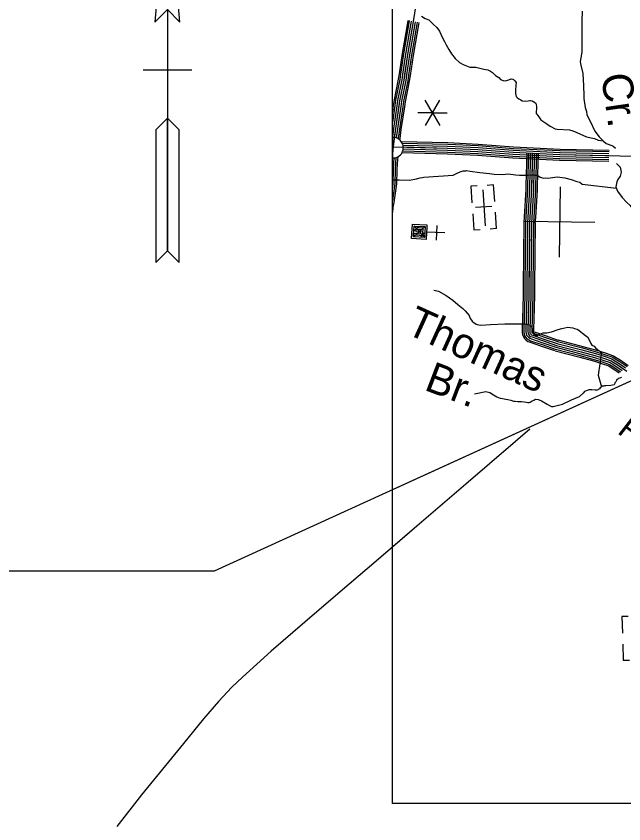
# Model space of a CAD drawing. Extents: x 1577619 to 1828281, y 483481 to 598136.
# Drawn here: x 1663305 to 1672781, y 507802 to 520403 of the extents above; entities that cross this region are included whole.
import ezdxf

# ---------------------------------------------------------------- set-up
doc = ezdxf.new("R2010")
doc.units = 0
for name, color, linetype in [('DESIGN - CENTERLINE - Proposed', 7, 'Continuous'), ('DESIGN - CENTERLINE - Proposed Text', 7, 'Continuous'), ('DESIGN - DRAINAGE - Bridges and Cross Drains Size Text', 7, 'Continuous'), ('DESIGN - ROW - Right-of-Way and Easement Labels', 7, 'Continuous'), ('DESIGN - SHEET - Linework', 7, 'Continuous'), ('DESIGN - TRAFFIC CONTROL PERMANENT - Signalization', 7, 'Continuous'), ('DESIGN - TRANSPORTATION - Text', 7, 'Continuous'), ('DESIGN - UTILITIES - Cable (Underground) with Text', 7, 'Continuous'), ('SURVEY - CENTERLINE - Preliminary Text', 7, 'Continuous'), ('SURVEY - CONTROL with Text', 7, 'Continuous'), ('SURVEY - DRAINAGE - Bridge Hydraulic Data - Points - Locators', 7, 'Continuous'), ('SURVEY - TRANSPORTATION - Roads', 7, 'Continuous'), ('SURVEY - VEGETATION - Features with Text', 7, 'Continuous')]:
    doc.layers.add(name, color=color, linetype=linetype)

msp = doc.modelspace()

# ---------------------------------------------------------------- linework, layer by layer
at = {"layer": 'DESIGN - CENTERLINE - Proposed'}
for p, q in [((1665664, 519561), (1665286, 519561)), ((1666042, 519561), (1665664, 519561))]:
    msp.add_line(p, q, dxfattribs=at)
msp.add_lwpolyline([(1665664, 522561), (1665468, 520309), (1665664, 520505), (1665860, 520309), (1665664, 522561), (1665664, 516743), (1665846, 516561), (1665846, 518631), (1665664, 518813), (1665482, 518631), (1665482, 516561), (1665664, 516743)], dxfattribs=at)
for points in [[(1665664, 520505), (1665860, 520309), (1665664, 522561)], [(1665482, 516561), (1665664, 516743), (1665664, 518813), (1665482, 518631)]]:
    msp.add_lwpolyline(points, close=True, dxfattribs=at)
at = {"layer": 'DESIGN - CENTERLINE - Proposed Text'}
for points in [[(1680381, 518131), (1666391, 511746), (1653607, 511746)], [(1680381, 518131), (1669172, 513015)]]:
    msp.add_lwpolyline(points, dxfattribs=at)
at = {"layer": 'DESIGN - SHEET - Linework'}
msp.add_lwpolyline([(1669172, 526511), (1695618, 526511), (1695618, 508120), (1669172, 508120)], close=True, dxfattribs=at)
at = {"layer": 'DESIGN - TRAFFIC CONTROL PERMANENT - Signalization'}
for q in [(1669682, 519092), (1669910, 519092), (1669568, 518894), (1669682, 518697), (1669910, 518697), (1670024, 518894)]:
    msp.add_line((1669796, 518894), q, dxfattribs=at)
at = {"layer": 'DESIGN - TRANSPORTATION - Text'}
for points in [[(1672130, 520479), (1672128, 520329), (1672128, 519976), (1672125, 519849), (1672116, 519781), (1672104, 519727), (1672099, 519693), (1672111, 519637), (1672140, 519508), (1672153, 519314), (1672156, 519167), (1672157, 519121), (1672178, 518978), (1672197, 518916), (1672203, 518864), (1672260, 518755), (1672328, 518610), (1672397, 518521), (1672431, 518482), (1672463, 518452), (1672506, 518419), (1672610, 518380), (1672651, 518344), (1672653, 518342)], [(1669628, 520403), (1669685, 520367), (1669739, 520344), (1669810, 520279), (1669865, 520226), (1669904, 520168), (1669949, 520073), (1669984, 520006), (1670009, 519954), (1670052, 519881), (1670095, 519814), (1670150, 519745), (1670220, 519678), (1670276, 519651), (1670326, 519630), (1670381, 519607), (1670471, 519608), (1670597, 519578), (1670662, 519567), (1670700, 519546), (1670732, 519526), (1670781, 519477), (1670832, 519444), (1670856, 519416), (1670898, 519399), (1670932, 519392), (1670988, 519409), (1671022, 519425), (1671050, 519418), (1671062, 519416), (1671083, 519392), (1671101, 519368), (1671098, 519324), (1671093, 519244), (1671094, 519198), (1671104, 519151), (1671118, 519133), (1671143, 519113), (1671173, 519100), (1671197, 519082), (1671253, 519077), (1671287, 519080), (1671315, 519086), (1671327, 519086), (1671349, 519081), (1671378, 519065), (1671402, 519050), (1671414, 519030), (1671419, 518988), (1671415, 518882), (1671425, 518872), (1671453, 518835), (1671486, 518787), (1671581, 518723), (1671630, 518688), (1671710, 518643), (1671740, 518641)], [(1671740, 518641), (1671934, 518632), (1671984, 518615), (1672046, 518589), (1672201, 518521), (1672323, 518492), (1672381, 518469), (1672458, 518456)], [(1672669, 518103), (1672725, 518046), (1672739, 517969), (1672723, 517906), (1672688, 517854), (1672670, 517820), (1672659, 517768), (1672657, 517741), (1672684, 517672), (1672755, 517575), (1672823, 517502), (1672880, 517449), (1672929, 517378), (1672965, 517332), (1672986, 517285), (1673043, 517170)], [(1669660, 517893), (1670118, 517924), (1670201, 517966), (1670247, 517981), (1670278, 517989), (1670318, 517992), (1670328, 517994), (1670383, 517987), (1670537, 517966), (1670687, 517948), (1670760, 517937), (1670896, 517934), (1670976, 517941), (1671090, 517927), (1671152, 517922), (1671218, 517921), (1671290, 517922), (1671340, 517927), (1671376, 517925), (1671400, 517922), (1671424, 517920)], [(1669172, 517851), (1669278, 517852), (1669438, 517846), (1669548, 517866), (1669604, 517883), (1669640, 517888), (1669660, 517893)], [(1671424, 517920), (1671455, 517907), (1671477, 517891), (1671495, 517887), (1671521, 517878), (1671567, 517879), (1671595, 517873)], [(1671595, 517873), (1671742, 517896), (1671860, 517881), (1671961, 517856), (1672047, 517825), (1672095, 517812), (1672131, 517784), (1672666, 517717)], [(1669820, 516130), (1669892, 516111), (1670013, 516046), (1670112, 515970), (1670195, 515905), (1670273, 515840), (1670306, 515806), (1670340, 515768), (1670369, 515731), (1670383, 515685), (1670406, 515661), (1670422, 515636), (1670440, 515624), (1670476, 515600), (1670496, 515594), (1670519, 515585), (1670553, 515581), (1670701, 515593), (1670927, 515605), (1671133, 515604), (1671217, 515603), (1671265, 515599), (1671289, 515590), (1671311, 515588), (1671323, 515578), (1671337, 515568), (1671356, 515527), (1671362, 515483), (1671367, 515457), (1671371, 515445), (1671385, 515435), (1671399, 515431), (1671429, 515423), (1671453, 515434), (1671479, 515446), (1671497, 515454), (1671523, 515461), (1671581, 515465), (1671655, 515478), (1671758, 515516)], [(1671758, 515516), (1671814, 515529), (1671906, 515550), (1671944, 515548), (1671988, 515541), (1672011, 515531), (1672035, 515527), (1672055, 515519), (1672077, 515506), (1672111, 515480), (1672136, 515458), (1672156, 515441), (1672190, 515415), (1672214, 515401), (1672233, 515365), (1672269, 515298), (1672282, 515272), (1672316, 515254), (1672338, 515227), (1672368, 515203), (1672403, 515183), (1672419, 515168), (1672431, 515158), (1672382, 514801), (1672435, 514621)], [(1672745, 514763), (1672719, 514757), (1672695, 514748), (1672685, 514738), (1672671, 514732), (1672665, 514718), (1672655, 514696), (1672639, 514684), (1672642, 514670), (1672630, 514652), (1672606, 514644), (1672580, 514643), (1672500, 514638), (1672478, 514636), (1672468, 514630), (1672460, 514630), (1672444, 514630), (1672430, 514616), (1672414, 514602), (1672404, 514591), (1672382, 514579), (1672378, 514575), (1672364, 514569), (1672352, 514569), (1672334, 514569), (1672282, 514572), (1672256, 514572), (1672240, 514572), (1672224, 514568), (1672194, 514559), (1672168, 514545), (1672148, 514523), (1672083, 514462)], [(1670453, 514513), (1670631, 514545), (1670689, 514531), (1670751, 514496), (1670802, 514465), (1670854, 514443), (1670888, 514436), (1670942, 514430), (1670972, 514423), (1671018, 514413), (1671058, 514398), (1671085, 514398), (1671129, 514393), (1671187, 514391), (1671227, 514388), (1671263, 514382), (1671285, 514375), (1671307, 514373), (1671321, 514381), (1671349, 514401), (1671375, 514414), (1671402, 514426), (1671444, 514424), (1671463, 514419), (1671495, 514403), (1671583, 514352), (1671624, 514327), (1671644, 514317), (1671654, 514313), (1671680, 514311), (1671827, 514349), (1671965, 514418), (1672091, 514469)]]:
    msp.add_lwpolyline(points, dxfattribs=at)
at = {"layer": 'DESIGN - UTILITIES - Cable (Underground) with Text'}
for p, q in [((1670494, 517756), (1670395, 517749)), ((1670395, 517749), (1670413, 517489)), ((1670750, 517770), (1670651, 517763)), ((1670768, 517514), (1670750, 517770)), ((1670723, 517436), (1670470, 517418)), ((1670425, 517318), (1670442, 517067)), ((1670798, 517088), (1670780, 517346)), ((1669860, 516909), (1669872, 517137)), ((1670442, 517067), (1670540, 517074)), ((1670798, 517088), (1670698, 517081)), ((1672749, 511036), (1672758, 510775)), ((1672849, 511039), (1672750, 511036)), ((1672764, 510604), (1672773, 510353)), ((1672773, 510353), (1672871, 510356))]:
    msp.add_line(p, q, dxfattribs=at)
for points in [[(1670580, 517694), (1670619, 517133)], [(1669710, 517033), (1669705, 517034), (1669699, 516920), (1669472, 516932), (1669484, 517159), (1669711, 517147), (1669702, 516977), (1669698, 516977)], [(1669688, 516977), (1669503, 516987), (1669511, 517129), (1669681, 517121), (1669672, 516950), (1669502, 516959), (1669505, 517016), (1669647, 517008), (1669651, 517094), (1669537, 517099), (1669535, 517042), (1669620, 517038), (1669621, 517067), (1669564, 517070)], [(1669679, 517120), (1669504, 516960)], [(1669591, 517124), (1669508, 517047)], [(1669672, 516948), (1669510, 517131)], [(1669668, 517024), (1669609, 516954)], [(1669990, 517021), (1669700, 517034)]]:
    msp.add_lwpolyline(points, dxfattribs=at)
at = {"layer": 'SURVEY - CENTERLINE - Preliminary Text'}
for points in [[(1671314, 513957), (1671092, 513767), (1670315, 513101), (1669552, 512446), (1668917, 511898), (1668359, 511424), (1667807, 510947), (1667284, 510496), (1666833, 510092), (1666669, 509932), (1666461, 509712), (1666227, 509442), (1665917, 509057), (1665635, 508711), (1665261, 508256), (1664876, 507762)], [(1671314, 513957), (1671092, 513767), (1670315, 513101), (1669552, 512446), (1668917, 511898), (1668359, 511424), (1667807, 510947), (1667284, 510496), (1666833, 510092), (1666669, 509932), (1666461, 509712), (1666227, 509442), (1665917, 509057), (1665635, 508711), (1665261, 508256), (1664876, 507762)], [(1671314, 513957), (1671092, 513767), (1670315, 513101), (1669552, 512446), (1669172, 512118)], [(1671314, 513957), (1671092, 513767), (1670315, 513101), (1669552, 512446), (1669172, 512118)]]:
    msp.add_lwpolyline(points, dxfattribs=at)
at = {"layer": 'SURVEY - CONTROL with Text'}
for points in [[(1669569, 520776), (1669492, 520287), (1669408, 519805), (1669350, 519403), (1669284, 519081), (1669220, 518648), (1669183, 518368), (1669172, 518254)], [(1669412, 520337), (1669406, 520301), (1669354, 520000)], [(1669436, 520333), (1669430, 520297), (1669378, 519995)], [(1669467, 520327), (1669461, 520292), (1669409, 519990)], [(1669497, 520322), (1669492, 520287), (1669439, 519985)], [(1669528, 520316), (1669522, 520282), (1669470, 519980)], [(1669558, 520311), (1669553, 520277), (1669500, 519974)], [(1669583, 520306), (1669578, 520273), (1669526, 519970)], [(1669354, 520000), (1669323, 519819), (1669277, 519503)], [(1669378, 519995), (1669347, 519815), (1669301, 519500)], [(1669409, 519990), (1669378, 519810), (1669332, 519495)], [(1669439, 519985), (1669408, 519805), (1669363, 519491)], [(1669470, 519980), (1669439, 519800), (1669393, 519486)], [(1669500, 519974), (1669469, 519795), (1669424, 519482)], [(1669526, 519970), (1669495, 519791), (1669449, 519478)], [(1669277, 519503), (1669264, 519418), (1669199, 519096), (1669186, 519012)], [(1669301, 519500), (1669289, 519413), (1669223, 519091), (1669211, 519008)], [(1669332, 519495), (1669319, 519408), (1669254, 519086), (1669241, 519004)], [(1669363, 519491), (1669350, 519403), (1669284, 519081), (1669272, 518999)], [(1669393, 519486), (1669380, 519397), (1669315, 519075), (1669303, 518995)], [(1669424, 519482), (1669411, 519392), (1669345, 519070), (1669333, 518990)], [(1669449, 519478), (1669436, 519388), (1669371, 519065), (1669359, 518986)], [(1669186, 519012), (1669172, 518913)], [(1669211, 519008), (1669172, 518746)], [(1669241, 519004), (1669189, 518653), (1669172, 518521)], [(1669272, 518999), (1669220, 518648), (1669201, 518510)], [(1669303, 518995), (1669250, 518644), (1669232, 518504)], [(1669333, 518990), (1669281, 518640), (1669262, 518496)], [(1669359, 518986), (1669306, 518636), (1669288, 518493)], [(1669231, 518501), (1669231, 518500)], [(1669262, 518496), (1669261, 518490)], [(1669288, 518493), (1669285, 518475)], [(1669310, 518449), (1670035, 518431), (1670512, 518408), (1671060, 518366), (1671788, 518330)], [(1669182, 518365), (1670032, 518345), (1670506, 518322), (1671055, 518280), (1671784, 518244)], [(1669324, 518424), (1670034, 518407), (1670510, 518384), (1671059, 518341), (1671787, 518306)], [(1669337, 518393), (1670033, 518376), (1670508, 518353), (1671057, 518311), (1671786, 518275)], [(1669341, 518331), (1670031, 518314), (1670505, 518291), (1671053, 518249), (1671782, 518213)], [(1669342, 518362), (1670032, 518345), (1670506, 518322), (1671055, 518280), (1671784, 518244)], [(1671786, 518330), (1672551, 518315)], [(1669197, 518192), (1669189, 518110), (1669186, 518006)], [(1669228, 518198), (1669220, 518108), (1669217, 518005)], [(1669255, 518209), (1669245, 518106), (1669243, 518005)], [(1669326, 518274), (1670029, 518257), (1670501, 518234), (1671050, 518192), (1671780, 518156)], [(1669334, 518300), (1670030, 518283), (1670503, 518260), (1671051, 518218), (1671781, 518182)], [(1671783, 518213), (1672547, 518197)], [(1671784, 518244), (1674139, 518195)], [(1671784, 518244), (1672548, 518228)], [(1671785, 518306), (1672550, 518290)], [(1671785, 518275), (1672549, 518259)], [(1671782, 518156), (1672545, 518140)], [(1671783, 518182), (1672546, 518166)], [(1669186, 518006), (1669181, 517794), (1669172, 517730)], [(1669217, 518005), (1669212, 517792), (1669172, 517525)], [(1669243, 518005), (1669238, 517789), (1669193, 517497)], [(1669193, 517497), (1669181, 517419), (1669172, 517340)]]:
    msp.add_lwpolyline(points, dxfattribs=at)
at = {"layer": 'SURVEY - DRAINAGE - Bridge Hydraulic Data - Points - Locators'}
for p, q in [((1671786, 517741), (1671775, 516641)), ((1672331, 517185), (1671231, 517197))]:
    msp.add_line(p, q, dxfattribs=at)
at = {"layer": 'SURVEY - TRANSPORTATION - Roads'}
for points in [[(1669172, 518347), (1669180, 518346)], [(1671268, 518267), (1671255, 517767)], [(1671293, 518266), (1671280, 517767)], [(1671355, 518265), (1671340, 517697), (1671308, 517179)], [(1671324, 518266), (1671311, 517766)], [(1671355, 518265), (1671342, 517765)], [(1671386, 518264), (1671373, 517764)], [(1671417, 518263), (1671404, 517763)], [(1671443, 518262), (1671429, 517763)], [(1671255, 517767), (1671253, 517700), (1671227, 517271)], [(1671280, 517767), (1671278, 517699), (1671251, 517270)], [(1671311, 517766), (1671309, 517698), (1671282, 517268)], [(1671342, 517765), (1671340, 517697), (1671313, 517266)], [(1671373, 517764), (1671371, 517695), (1671344, 517264)], [(1671404, 517763), (1671402, 517694), (1671375, 517262)], [(1671429, 517763), (1671427, 517693), (1671401, 517260)], [(1671221, 517180), (1671217, 516680)], [(1671227, 517271), (1671221, 517184)], [(1671246, 517179), (1671242, 516679)], [(1671251, 517270), (1671246, 517183)], [(1671277, 517179), (1671273, 516679)], [(1671282, 517268), (1671277, 517181)], [(1671308, 517179), (1671298, 516045), (1671283, 515521), (1671284, 515480), (1671287, 515456), (1671292, 515440), (1671300, 515430), (1671312, 515417), (1671328, 515406), (1671350, 515398), (1671408, 515377), (1671730, 515267)], [(1671308, 517179), (1671304, 516679)], [(1671313, 517266), (1671308, 517179)], [(1671339, 517179), (1671335, 516679)], [(1671344, 517264), (1671339, 517177)], [(1671370, 517178), (1671366, 516678)], [(1671375, 517262), (1671370, 517175)], [(1671396, 517178), (1671391, 516678)], [(1671401, 517260), (1671395, 517173)], [(1671217, 516680), (1671212, 516180)], [(1671242, 516679), (1671237, 516179)], [(1671273, 516679), (1671268, 516179)], [(1671304, 516679), (1671299, 516179)], [(1671335, 516679), (1671330, 516179)], [(1671366, 516678), (1671361, 516178)], [(1671391, 516678), (1671387, 516178)], [(1671212, 516180), (1671211, 516047), (1671201, 515681)], [(1671237, 516179), (1671236, 516046), (1671226, 515681)], [(1671268, 516179), (1671267, 516046), (1671257, 515680)], [(1671299, 516179), (1671298, 516045), (1671288, 515679)], [(1671330, 516179), (1671329, 516044), (1671319, 515678)], [(1671361, 516178), (1671360, 516044), (1671350, 515677)], [(1671387, 516178), (1671386, 516043), (1671375, 515677)], [(1671201, 515681), (1671197, 515521), (1671198, 515475), (1671201, 515437), (1671215, 515398), (1671234, 515374), (1671254, 515352), (1671286, 515329), (1671320, 515316), (1671379, 515295), (1671498, 515254)], [(1671226, 515681), (1671221, 515521), (1671222, 515476), (1671226, 515443), (1671237, 515410), (1671253, 515390), (1671271, 515371), (1671298, 515351), (1671328, 515339), (1671387, 515318), (1671506, 515278)], [(1671257, 515680), (1671252, 515521), (1671253, 515478), (1671256, 515450), (1671265, 515425), (1671277, 515410), (1671292, 515394), (1671313, 515378), (1671339, 515369), (1671397, 515348), (1671516, 515307)], [(1671288, 515679), (1671283, 515521), (1671284, 515480), (1671287, 515456), (1671292, 515440), (1671300, 515430), (1671312, 515417), (1671328, 515406), (1671350, 515398), (1671408, 515377), (1671526, 515336)], [(1671319, 515678), (1671314, 515521), (1671315, 515482), (1671317, 515463), (1671320, 515456), (1671324, 515450), (1671333, 515441), (1671343, 515433), (1671361, 515427), (1671418, 515406), (1671536, 515366)], [(1671350, 515677), (1671345, 515520), (1671346, 515484), (1671348, 515470), (1671348, 515470), (1671354, 515464), (1671358, 515461), (1671371, 515456), (1671428, 515435), (1671546, 515395)], [(1671375, 515677), (1671371, 515520), (1671372, 515485), (1671372, 515483), (1671380, 515480), (1671437, 515460), (1671555, 515419)], [(1671555, 515419), (1671759, 515350)], [(1671516, 515307), (1671720, 515237)], [(1671526, 515336), (1671730, 515267)], [(1671536, 515366), (1671740, 515296)], [(1671546, 515395), (1671750, 515325)], [(1671738, 515297), (1672126, 515197), (1672340, 515138), (1672472, 515097), (1672595, 515055), (1672632, 515032), (1672692, 514995), (1672805, 514916)], [(1671746, 515327), (1672134, 515227), (1672349, 515168), (1672482, 515126), (1672608, 515083), (1672648, 515059), (1672709, 515021), (1672831, 514935)], [(1671752, 515351), (1672141, 515251), (1672356, 515191), (1672490, 515150), (1672619, 515106), (1672661, 515080), (1672723, 515042), (1672851, 514952)], [(1671498, 515254), (1671702, 515185)], [(1671506, 515278), (1671710, 515208)], [(1671708, 515182), (1672096, 515082), (1672307, 515024), (1672435, 514984), (1672545, 514947), (1672570, 514931), (1672627, 514896), (1672708, 514839)], [(1671715, 515207), (1672102, 515107), (1672314, 515048), (1672443, 515009), (1672556, 514970), (1672583, 514953), (1672641, 514917), (1672730, 514855)], [(1671723, 515237), (1672110, 515137), (1672323, 515078), (1672453, 515038), (1672569, 514998), (1672599, 514980), (1672658, 514943), (1672755, 514875)], [(1671730, 515267), (1672118, 515167), (1672331, 515108), (1672463, 515067), (1672582, 515027), (1672616, 515006), (1672675, 514969), (1672826, 514863)], [(1671730, 515267), (1672118, 515167), (1672331, 515108), (1672463, 515067), (1672582, 515027), (1672616, 515006), (1672675, 514969), (1672780, 514895)]]:
    msp.add_lwpolyline(points, dxfattribs=at)
at = {"layer": 'SURVEY - VEGETATION - Features with Text'}
msp.add_line((1669172, 518511), (1669172, 518192), dxfattribs=at)
msp.add_lwpolyline([(1669172, 518192), (1669195, 518191), (1669217, 518195), (1669236, 518200), (1669257, 518210), (1669279, 518224), (1669297, 518238), (1669313, 518257), (1669326, 518275), (1669332, 518295), (1669339, 518317), (1669342, 518339), (1669342, 518358), (1669339, 518385), (1669334, 518406), (1669325, 518423), (1669316, 518439), (1669306, 518454), (1669292, 518469), (1669277, 518481), (1669263, 518490), (1669246, 518498), (1669231, 518504), (1669212, 518509), (1669185, 518512), (1669172, 518511)], dxfattribs=at)

# ---------------------------------------------------------------- texts
at = {"layer": 'DESIGN - DRAINAGE - Bridges and Cross Drains Size Text'}
for s, rotation, p in [('Cr.', 278.1803, (1672425, 519484)), ('Thomas', 335.6246, (1669359, 515463)), ('Br.', 339.15, (1669651, 514578))]:
    msp.add_text(s, height=475, rotation=rotation, dxfattribs=at).set_placement(p)
at = {"layer": 'DESIGN - ROW - Right-of-Way and Easement Labels'}
msp.add_text('PETTY', height=370, rotation=322.139, dxfattribs=at).set_placement((1672664, 513907))

doc.saveas('drawing.dxf')
